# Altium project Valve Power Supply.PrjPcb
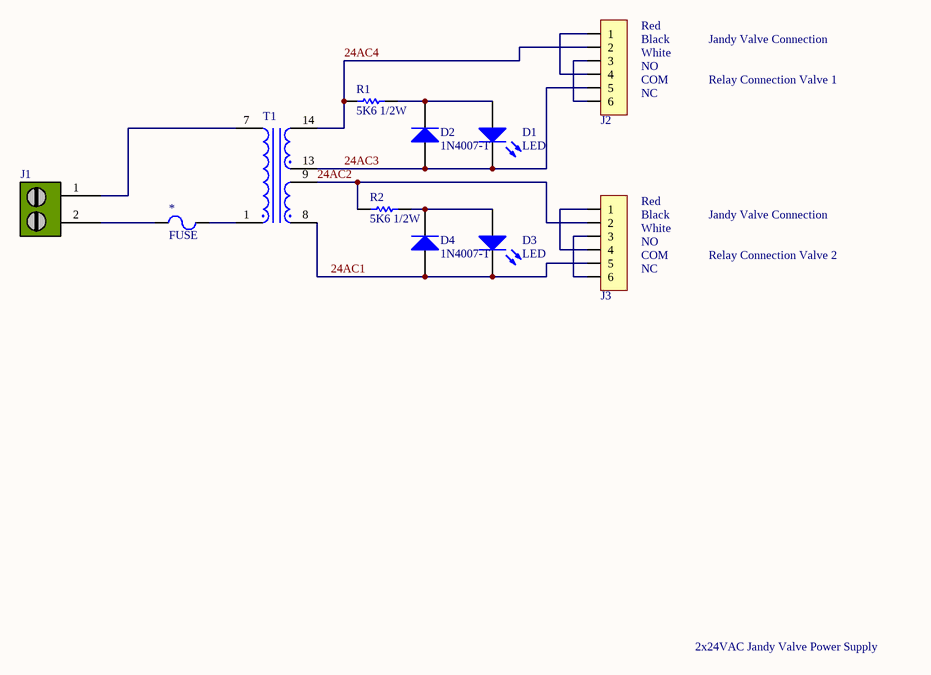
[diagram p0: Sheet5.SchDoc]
1 sheet, 11 parts. Net scope: global (net labels, ports and power ports of the same name join across sheets).

## Sheet Sheet5.SchDoc
size A4

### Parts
*  FUSE  [PCB-0iyy32dpt2l6vl18xoym-1]
D1  LED  [PCB-6hmn14p3euwrtpae4j9f-1]
D2  1N4007-T  [DIOD-DO-41-P-2_V]
D3  LED  [PCB-6hmn14p3euwrtpae4j9f-1]
D4  1N4007-T  [DIOD-DO-41-P-2_V]
J1  TE Connectivity 282857-2  [PCB-rsrshy9k52pas9f32mx6-1]  (value not drawn)
J2  Phoenix Contact 1757284  [PCB-gbrv0pb25lbd555ym6el-1]  (value not drawn)
J3  Phoenix Contact 1757284  [PCB-gbrv0pb25lbd555ym6el-1]  (value not drawn)
R1  5K6 1/2W  [PCB-j1411vnnromljbd863ui-1]
R2  5K6 1/2W  [PCB-j1411vnnromljbd863ui-1]
T1  YHDC PCB Transformer. 230VAC Primary, 2x24VAC Secondary  [PCB-4cme8jnyrntyvyjelfo4-1]  (value not drawn)

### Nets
24AC1: D3.2(K) D4.1(A) J3.5 T1.8
24AC2: J3.2 R2.1 T1.9
24AC3: D1.2(K) D2.1(A) J2.5 T1.13
24AC4: J2.2 R1.1 T1.14
Net*_1: *.1 J1.2
Net*_2: *.2 T1.1
NetD1_1: D1.1(A) D2.2(K) R1.2
NetD3_1: D3.1(A) D4.2(K) R2.2
NetJ1_1: J1.1 T1.7
NetJ2_1: J2.1 J2.4
NetJ2_3: J2.3 J2.6
NetJ3_1: J3.1 J3.4
NetJ3_3: J3.3 J3.6

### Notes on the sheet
- (near J2) Red
- (near J2) Black
- Jandy Valve Connection
- (near J2) White
- (near J2) NO
- (near J2) COM
- (near J2) NC
- Relay Connection Valve 1
- (near J3) Red
- (near J3) Black
- (near J3) White
- (near J3) NO
- (near J3) COM
- (near J3) NC
- Relay Connection Valve 2
- 2x24VAC Jandy Valve Power Supply

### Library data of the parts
* = CMP-978d5de5678c484a-3: Fuse Holder, 250 V, 10 A, Cartridge Fuse Holder, Through Hole, 1; Manufacturer Part Number: 696108003002
D1 D3 = CMP-9d1f5758637d42d8-1: TLHR5205 Red LED, 625 nm 5mm (T-1 3/4), Round Lens Through Hole package; Peak Wavelength: 635 nm; Wavelength: 625 nm; Lead-Free Status: Lead Free; Luminous Intensity: 70.0 mcd; Viewing Angle: 14 °; Lead Length: 24.0 mm; Voltage Rating (DC): 2.00 V
D2 D4 = CMP-815216-8: 1.0 A Rectifier, 8 pF, 1000 V, -65 to 150 degC, 2-Pin DO-41 Plastic, RoHS, Tape and Reel; Lead-Free Status: Lead Free; Current Rating: 1.0 A; Capacitance: 8e-12 F; Polarity: Standard; Voltage Rating (DC): 1000.0 V
J1 = CMP-6678ad2915e7b9bf-2: Wire to Board 2 Position 5.08 mm Pitch 30-12 AWG Euro Style Terminal Block; Number of Contacts: 2; Pin Pitch: 5.08 mm; Lead-Free Status: Lead Free; ELV Compliant: Compliant
J2 J3 = CMP-3802f109acaee7c5-1: Terminal Header; 12 A; 250 V; 5.08 mm; 6; Solder Mount; 1.4 mm; 4 kV; 320 V; Number of Contacts: 6; Pin Pitch: 5.08 mm; Lead-Free Status: Lead Free; Voltage Rating (AC): 250 V; Voltage Rating (DC): 320 V; Gender: Male; Mounting Angle: 90.0 °; Current Rating: 12.0 A
R1 R2 = CMP-cf680747e65110af-1: Res Carbon Film 5.6K Ohm 5% 1/2W -400ppm/°C to 0ppm/°C Conformal AXL Thru-Hole T/R
T1 = CMP-buw0ev2etz0pkjsi8ng8-2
